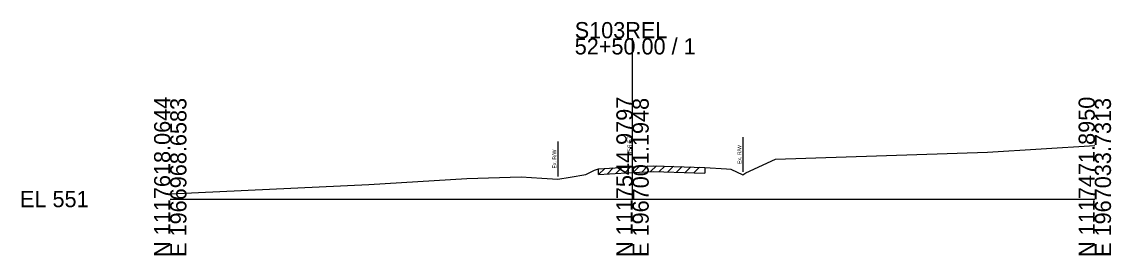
# Model space of a CAD drawing. Extents: x -26 to 163, y -10 to 24518.
# Drawn here: x -25.7 to 162.8, y 2990.3 to 3030.6 of the extents above; entities that cross this region are included whole.
import ezdxf

# ---------------------------------------------------------------- set-up
doc = ezdxf.new("R2010")
doc.units = 0
for name, color, linetype in [('RD_GPK_XS_Cell', 7, 'Continuous'), ('RD_XS_ExGround', 7, 'Continuous'), ('RD_XS_ExPaveRet', 7, 'Continuous'), ('RD_XS_ExRW', 7, 'Continuous'), ('RD_XS_TX_Elev_EX', 7, 'Continuous')]:
    doc.layers.add(name, color=color, linetype=linetype)

msp = doc.modelspace()

# ---------------------------------------------------------------- linework, layer by layer
at = {"layer": 'RD_GPK_XS_Cell'}
for p, q in [((80, 3000), (80, 3027.79)), ((0, 3000), (80, 3000)), ((80, 3000), (160, 3000))]:
    msp.add_line(p, q, dxfattribs=at)
at = {"layer": 'RD_XS_ExGround'}
msp.add_lwpolyline([(0, 3000.88), (34.35, 3002.54), (51.3, 3003.55), (60.7, 3003.83), (64.3, 3003.59), (67.05, 3003.43), (69.22, 3003.8), (71.9, 3004.26), (73.43, 3004.97), (74.11, 3005.23), (76.02, 3005.35), (80, 3005.57), (83.7, 3005.77), (90.67, 3005.54), (92.51, 3005.48), (96.28, 3005.21), (96.99, 3005.17), (99.07, 3004.2), (99.63, 3004.52), (104.73, 3006.92), (141.44, 3008.1), (160, 3009.26)], dxfattribs=at)
at = {"layer": 'RD_XS_ExPaveRet'}
for p, q in [((74.11, 3004.23), (75.18, 3005.3)), ((74.11, 3004.23), (74.11, 3005.23)), ((75.61, 3004.33), (76.67, 3005.39)), ((77.11, 3004.41), (78.17, 3005.47)), ((78.61, 3004.49), (79.67, 3005.55)), ((80.11, 3004.58), (81.17, 3005.64)), ((81.61, 3004.66), (82.67, 3005.72)), ((83.11, 3004.74), (84.13, 3005.76)), ((84.61, 3004.74), (85.58, 3005.71)), ((86.11, 3004.69), (87.08, 3005.66)), ((87.61, 3004.64), (88.58, 3005.61)), ((89.11, 3004.59), (90.08, 3005.56)), ((90.61, 3004.54), (91.59, 3005.51)), ((92.51, 3005.48), (92.51, 3004.48)), ((74.11, 3004.23), (76.02, 3004.35)), ((76.02, 3004.35), (80, 3004.57)), ((80, 3004.57), (83.7, 3004.77)), ((83.7, 3004.77), (90.67, 3004.54)), ((90.67, 3004.54), (92.51, 3004.48))]:
    msp.add_line(p, q, dxfattribs=at)
at = {"layer": 'RD_XS_ExRW'}
for p, q in [((67.05, 3009.93), (67.05, 3003.93)), ((99.07, 3010.7), (99.07, 3004.7)), ((99.07, 3010.7), (99.07, 3004.7))]:
    msp.add_line(p, q, dxfattribs=at)

# ---------------------------------------------------------------- texts
at = {"layer": 'RD_GPK_XS_Cell'}
for s, p in [('S103REL', (70, 3027.79)), ('52+50.00 / 1', (70, 3024.99)), ('EL 551', (-26, 2998.6))]:
    msp.add_text(s, height=2.8, dxfattribs=at).set_placement(p)
for s, p in [('N 1117618.0644', (0, 2990)), ('E 1966968.6583', (2.8, 2990)), ('N 1117544.9797', (80, 2990)), ('E 1967001.1948', (82.8, 2990)), ('N 1117471.8950', (160, 2990)), ('E 1967033.7313', (162.8, 2990))]:
    msp.add_text(s, height=2.8, rotation=90, dxfattribs=at).set_placement(p)
at = {"layer": 'RD_XS_ExRW'}
for p in [(98.82, 3006.04), (98.82, 3006.04), (66.8, 3005.27)]:
    msp.add_text('Ex. R/W ', height=0.65, rotation=90, dxfattribs=at).set_placement(p)
at = {"layer": 'RD_XS_TX_Elev_EX'}
msp.add_text('556.57', height=0.8, rotation=90, dxfattribs=at).set_placement((79.9, 3007.57))

doc.saveas('drawing.dxf')
